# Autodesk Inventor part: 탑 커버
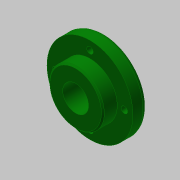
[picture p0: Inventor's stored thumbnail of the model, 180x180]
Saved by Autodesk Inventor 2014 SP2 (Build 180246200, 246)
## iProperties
Created: 2016-08
Part Number: 탑 커버
Material: 알루미늄 6061
Document SubType Name: Modeling
Designer: mduedu
Density: 2.71 g/cm^3
Appearance: 진녹색
Author: mduedu
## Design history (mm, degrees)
sketch "스케치1"
  geometry: L1 (0, 0)-(0, 10); L2 (0, 10)-(-30, 10); L3 (-30, 10)-(-30, 0); L4 (-30, 0)-(-19, 0); L5 (-19, 0)-(-19, -10); L6 (-19, -10)-(0, -10); L7 (0, -10)-(0, 10); 2 further points
  constraints: 14 end point, 3 parallel, 3 perpendicular, 1 coincident, 1 horizontal alignment, 1 midpoint, 1 vertical
  dimensions: "d0" = 10 distance of L1.start L1.end; "d2" = 60 diameter of L3 L1; "d3" = 38 diameter of L5 L1; "d4" = 20 distance between parallel lines of L6 L2
revolve "회전1" sketch "스케치1" stored, may be unused: angle "d5" = 90 deg
hole "구멍1" diameter "d8" = 18; stored, may be unused: countersink angle "d12" = 90 deg, drill point angle "d14" = 118 deg; dims "d6" = 10, "d7" = 10, "d9" = 6, "d10" = 4, "d11" = 2, "d13" = 8
chamfer "모따기1" distance "d15" = 1; stored, may be unused: second distance "d16" = 2, angle "d17" = 45 deg
chamfer "모따기2" distance "d18" = 1; stored, may be unused: second distance "d19" = 2, angle "d20" = 45 deg
fillet "모깎기1" dims "d21" = 3
sketch "스케치2" dims "d22" = 48
  geometry: 6 further points
  constraints: 2 vertical alignment, 1 coincident, 7 other
  dimensions: "d26" = 360 deg dimension on point (0, 0) point (0, 24) (derived)
sketch "스케치3"
  geometry: 4 further points
hole "구멍2" sketch "스케치3" at (-24, 0), (0, -24), (24, 0), (0, 24) diameter "d28" = 4.5; stored, may be unused: countersink angle "d32" = 90 deg, drill point angle "d34" = 0 deg; dims "d29" = 6, "d30" = 8, "d31" = 4.6, "d33" = 8
node "솔리드1"
